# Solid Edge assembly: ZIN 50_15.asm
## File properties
Title: Zylinder
Author: bmolnar
Template: iso metric assembly.asm
Last saved by: bmolnar
Revision: 9
Application: Solid Edge
Username: bmolnar
Dokumentum tartalom típus: 1
Document Number: ZIN 50/15
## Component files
Profilrohr.par
Kolbenstange.par
Kit_2.par
Kit_1.par
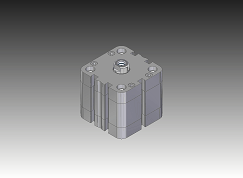
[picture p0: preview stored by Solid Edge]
